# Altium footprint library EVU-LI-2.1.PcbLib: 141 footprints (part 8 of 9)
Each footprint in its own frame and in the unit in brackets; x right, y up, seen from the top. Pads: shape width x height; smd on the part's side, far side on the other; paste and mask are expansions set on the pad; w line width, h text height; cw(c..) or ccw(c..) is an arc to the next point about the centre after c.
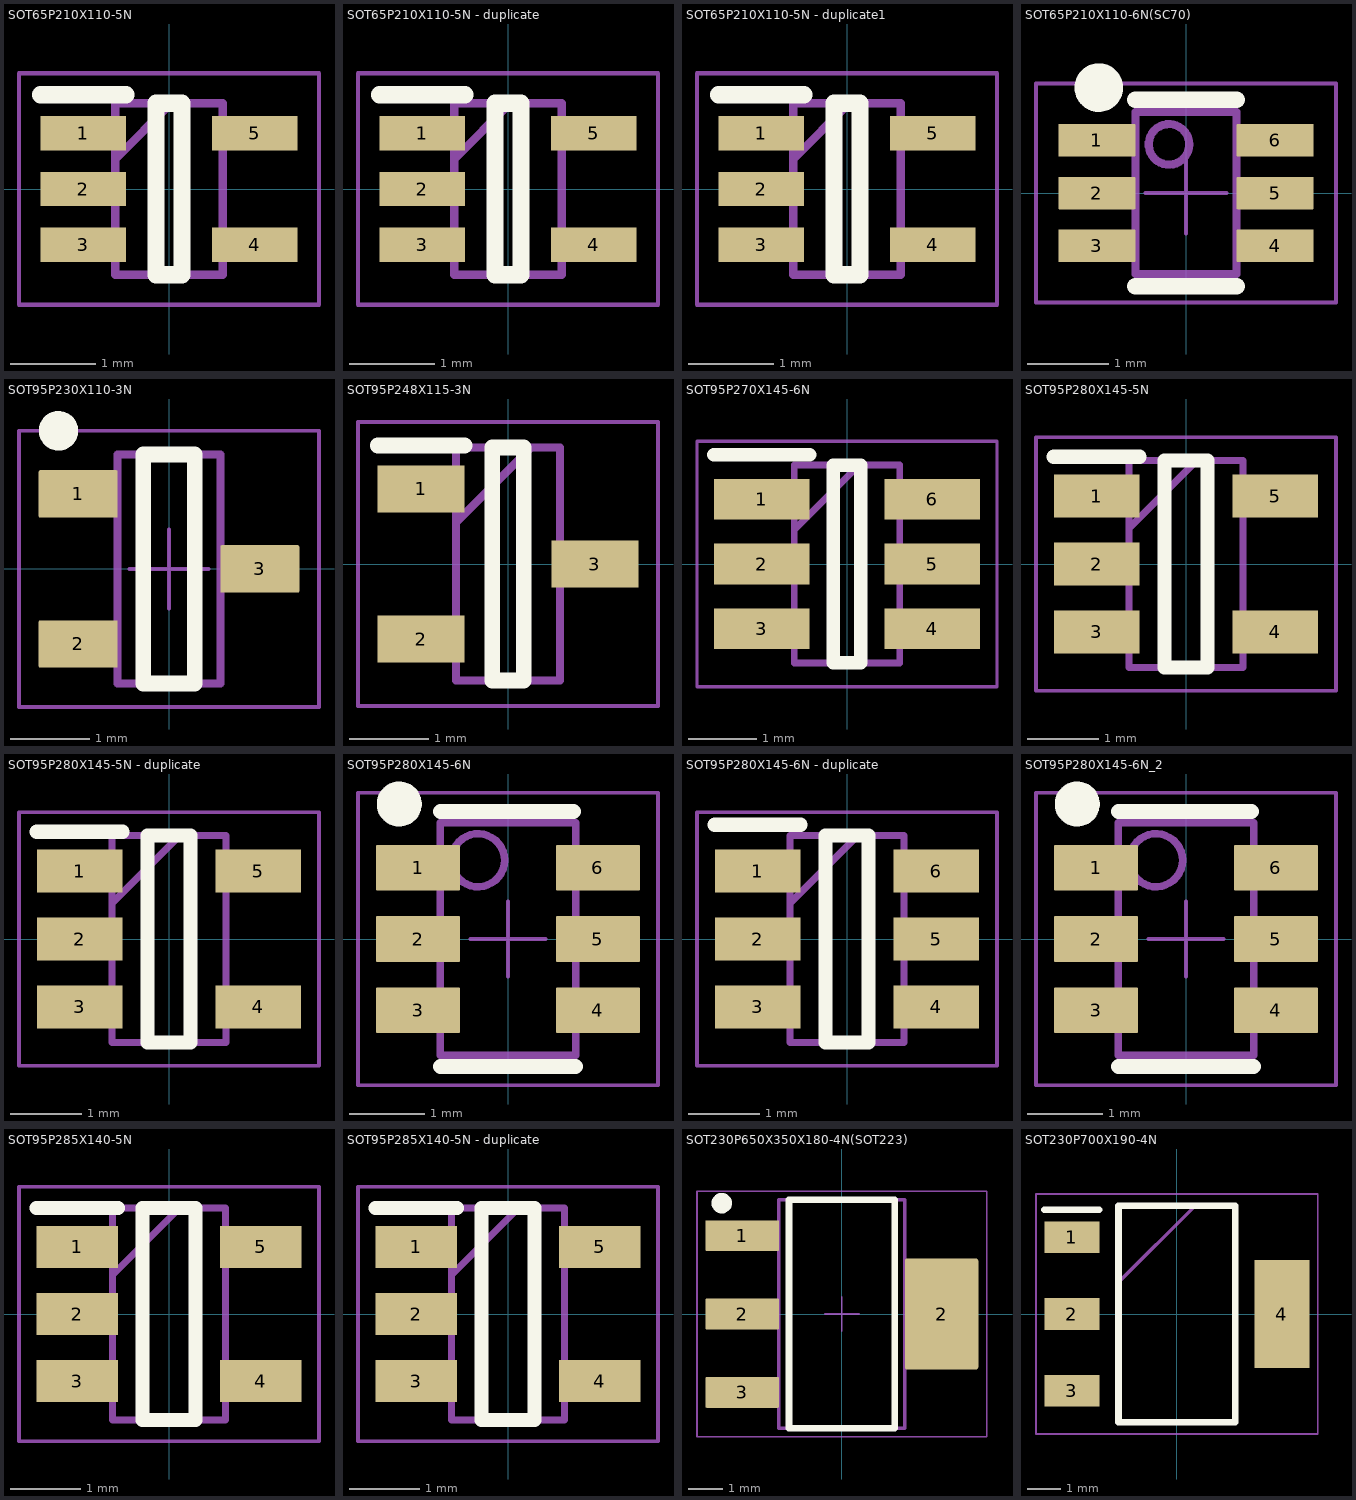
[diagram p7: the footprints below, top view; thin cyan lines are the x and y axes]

## SOT65P210X110-5N [mm]
pads (5):
  rect 1x0.4 smd: 1(-1,0.65) 2(-1,0) 3(-1,-0.65) 4(1,-0.65) 5(1,0.65)
Top Overlay:
  lines w0.2: -1.5,1.1 -0.5,1.1 ; -0.15,-1 -0.15,1 0.15,1 0.15,-1 -0.15,-1
Mechanical 13:
  lines w0.1: -0.625,0.35 0.025,1 ; -0.625,-1 -0.625,1 0.625,1 0.625,-1 -0.625,-1
Top Courtyard:
  lines w0.05: -1.75,-1.35 -1.75,1.35 1.75,1.35 1.75,-1.35 -1.75,-1.35
3D body "ZXRE160H5TA.stp": height 1.1, standoff 0, extent -1.05,-1 1.05,1

## SOT65P210X110-5N - duplicate [mm]
pads (5):
  rect 1x0.4 smd: 1(-1,0.65) 2(-1,0) 3(-1,-0.65) 4(1,-0.65) 5(1,0.65)
Top Overlay:
  lines w0.2: -1.5,1.1 -0.5,1.1 ; -0.15,-1 0.15,-1 0.15,1 -0.15,1 -0.15,-1
Mechanical 13:
  lines w0.1: -0.625,0.35 0.025,1 ; -0.625,-1 0.625,-1 0.625,1 -0.625,1 -0.625,-1
Top Courtyard:
  lines w0.05: -1.75,-1.35 1.75,-1.35 1.75,1.35 -1.75,1.35 -1.75,-1.35
3D body "ZXRE160H5TA.stp": height 1.1, standoff 0, extent -1.05,-1 1.05,1

## SOT65P210X110-5N - duplicate1 [mm]
pads (5):
  rect 1x0.4 smd: 1(-1,0.65) 2(-1,0) 3(-1,-0.65) 4(1,-0.65) 5(1,0.65)
Top Overlay:
  lines w0.2: -1.5,1.1 -0.5,1.1 ; -0.15,-1 -0.15,1 0.15,1 0.15,-1 -0.15,-1
Assembly Notes:
  lines w0.1: -0.625,0.35 0.025,1 ; -0.625,-1 -0.625,1 0.625,1 0.625,-1 -0.625,-1
Top Courtyard:
  lines w0.05: -1.75,-1.35 -1.75,1.35 1.75,1.35 1.75,-1.35 -1.75,-1.35
3D body "ZXRE160H5TA.stp": height 1.1, standoff 0, extent -1.05,-1 1.05,1

## SOT65P210X110-6N(SC70) [mm]
height 1.1
pads (6):
  rrect5% 0.95x0.4 smd mask+0.07: 1(-1.1,0.65) 2(-1.1,0) 3(-1.1,-0.65) 4(1.1,-0.65) 5(1.1,0) 6(1.1,0.65)
Top Overlay:
  circle w0.3: c-1.075,1.3 r0.15
  lines w0.2: -0.625,-1.15 0.625,-1.15 ; -0.625,1.15 0.625,1.15
Top Assembly:
  circle w0.1: c-0.21,0.6 r0.25
  lines w0.1: -0.625,-1 -0.625,1 0.625,1 0.625,-1 -0.625,-1
Top Designator:
  text ".Designator" at 0.3,-3.25 h1.5
Mechanical 9:
  text ".MARK" at 0.254,-1.778 h1.2
Top Courtyard:
  lines w0.05: -0.5,0 0.5,0 ; 0,-0.5 0,0.5 ; -1.85,-1.35 -1.85,1.35 1.85,1.35 1.85,-1.35 -1.85,-1.35
3D body: height 1.11, standoff 1.1, extent -0.473,0.376 0.025,0.875
3D body "SOT23-6-65P(DCK).STEP": height 1.1, standoff 0, extent -1.2,-1.05 1.2,1.05

## SOT95P230X110-3N [mm] "SOT95P230X110-3N"
height 1.1
pads (3):
  rrect5% 1x0.6 smd mask+0.05: 1(-1.15,0.95) 2(-1.15,-0.95) 3(1.15,0)
Top Overlay:
  circle w0.25: c-1.4,1.75 r0.125
  lines w0.2: -0.325,-1.45 0.325,-1.45 0.325,1.45 -0.325,1.45 -0.325,-1.45
Top Assembly:
  lines w0.1: -0.65,-1.45 0.65,-1.45 0.65,1.45 -0.65,1.45 -0.65,-1.45
Top Designator:
  text ".Designator" at -3.381,-0.211 h1.5
Mechanical 9:
  text ".MARK" at 0.329,-1.778 h1.2
Top Courtyard:
  lines w0.05: -0.5,0 0.5,0 ; 0,-0.5 0,0.5 ; -1.9,-1.75 1.9,-1.75 1.9,1.75 -1.9,1.75 -1.9,-1.75
3D body "SOT-23.STEP": height 1.1, standoff 0, extent -1.35,-1.55 1.35,1.55

## SOT95P248X115-3N [mm]
pads (3):
  rect 1.1x0.6 smd: 1(-1.1,0.95) 2(-1.1,-0.95) 3(1.1,0)
Top Overlay:
  lines w0.2: -1.65,1.5 -0.55,1.5 ; -0.2,-1.475 -0.2,1.475 0.2,1.475 0.2,-1.475 -0.2,-1.475
Mechanical 13:
  lines w0.1: -0.658,0.525 0.292,1.475 ; -0.658,-1.475 -0.658,1.475 0.658,1.475 0.658,-1.475 -0.658,-1.475
Top Courtyard:
  lines w0.05: -1.9,-1.8 -1.9,1.8 1.9,1.8 1.9,-1.8 -1.9,-1.8
3D body "BZX84C4V7-E3-08.stp": height 1.15, standoff 0, extent -1.238,-1.475 1.238,1.475

## SOT95P270X145-6N [mm]
pads (6):
  rect 1.4x0.6 smd: 1(-1.25,0.95) 2(-1.25,0) 3(-1.25,-0.95) 4(1.25,-0.95) 5(1.25,0) 6(1.25,0.95)
Top Overlay:
  lines w0.2: -1.95,1.6 -0.55,1.6 ; -0.2,-1.45 -0.2,1.45 0.2,1.45 0.2,-1.45 -0.2,-1.45
Mechanical 13:
  lines w0.1: -0.775,0.5 0.175,1.45 ; -0.775,-1.45 -0.775,1.45 0.775,1.45 0.775,-1.45 -0.775,-1.45
Top Courtyard:
  lines w0.05: -2.2,-1.8 -2.2,1.8 2.2,1.8 2.2,-1.8 -2.2,-1.8
3D body "93LC56BT-E_OT.stp": height 1.45, standoff 0, extent -1.35,-1.45 1.35,1.45

## SOT95P280X145-5N [mm]
pads (5):
  rect 1.2x0.6 smd: 1(-1.25,0.95) 2(-1.25,0) 3(-1.25,-0.95) 4(1.25,-0.95) 5(1.25,0.95)
Top Overlay:
  lines w0.2: -1.85,1.5 -0.65,1.5 ; -0.3,-1.45 0.3,-1.45 0.3,1.45 -0.3,1.45 -0.3,-1.45
Mechanical 13:
  lines w0.1: -0.8,0.5 0.15,1.45 ; -0.8,-1.45 0.8,-1.45 0.8,1.45 -0.8,1.45 -0.8,-1.45
Top Courtyard:
  lines w0.05: -2.1,-1.775 2.1,-1.775 2.1,1.775 -2.1,1.775 -2.1,-1.775
3D body "LMV331IDBVR.stp": height 1.2, standoff 0, extent -1.4,-1.45 1.4,1.45

## SOT95P280X145-5N - duplicate [mm]
pads (5):
  rect 1.2x0.6 smd: 1(-1.25,0.95) 2(-1.25,0) 3(-1.25,-0.95) 4(1.25,-0.95) 5(1.25,0.95)
Top Overlay:
  lines w0.2: -1.85,1.5 -0.65,1.5 ; -0.3,-1.45 -0.3,1.45 0.3,1.45 0.3,-1.45 -0.3,-1.45
Mechanical 13:
  lines w0.1: -0.8,0.5 0.15,1.45 ; -0.8,-1.45 -0.8,1.45 0.8,1.45 0.8,-1.45 -0.8,-1.45
Top Courtyard:
  lines w0.05: -2.1,-1.775 -2.1,1.775 2.1,1.775 2.1,-1.775 -2.1,-1.775
3D body "LMV331IDBVR.stp": height 1.2, standoff 0, extent -1.4,-1.45 1.4,1.45

## SOT95P280X145-6N [mm]
pads (6):
  rrect5% 1.12x0.61 smd mask+0.05: 1(-1.2,0.95) 2(-1.2,0) 3(-1.2,-0.95) 4(1.2,-0.95) 5(1.2,0) 6(1.2,0.95)
Top Overlay:
  circle w0.3: c-1.45,1.8 r0.15
  lines w0.2: -0.9,-1.7 0.9,-1.7 ; -0.9,1.7 0.875,1.7
Top Assembly:
  circle w0.1: c-0.4,1.05 r0.354
  lines w0.1: -0.9,-1.55 -0.9,1.55 0.9,1.55 0.9,-1.55 -0.9,-1.55
Top Designator:
  text ".Designator" at -3.25,-0.3 h1.5
Mechanical 9:
  text ".MARK" at 0.45,-1.675 h1.2
Top Courtyard:
  lines w0.05: -0.5,0 0.5,0 ; 0,-0.5 0,0.5 ; -2,-1.95 -2,1.95 2,1.95 2,-1.95 -2,-1.95
3D body "SOT-23-6_DBV.STEP": height 1.45, standoff 0, extent -1.417,-1.55 1.418,1.55
3D body: height 1.46, standoff 1.45, extent -0.498,0.801 0,1.3

## SOT95P280X145-6N - duplicate [mm]
pads (6):
  rect 1.2x0.6 smd: 1(-1.25,0.95) 2(-1.25,0) 3(-1.25,-0.95) 4(1.25,-0.95) 5(1.25,0) 6(1.25,0.95)
Top Overlay:
  lines w0.2: -1.85,1.6 -0.65,1.6 ; -0.3,-1.45 -0.3,1.45 0.3,1.45 0.3,-1.45 -0.3,-1.45
Mechanical 13:
  lines w0.1: -0.8,0.5 0.15,1.45 ; -0.8,-1.45 -0.8,1.45 0.8,1.45 0.8,-1.45 -0.8,-1.45
Top Courtyard:
  lines w0.05: -2.1,-1.775 -2.1,1.775 2.1,1.775 2.1,-1.775 -2.1,-1.775
3D body "LMR51610XDBVR.stp": height 1.45, standoff 0, extent -1.4,-1.45 1.4,1.45

## SOT95P280X145-6N_2 [mm]
pads (6):
  rrect5% 1.12x0.61 smd mask+0.05: 1(-1.2,0.95) 2(-1.2,0) 3(-1.2,-0.95) 4(1.2,-0.95) 5(1.2,0) 6(1.2,0.95)
Top Overlay:
  circle w0.3: c-1.45,1.8 r0.15
  lines w0.2: -0.9,-1.7 0.9,-1.7 ; -0.9,1.7 0.875,1.7
Top Assembly:
  circle w0.1: c-0.4,1.05 r0.354
  lines w0.1: -0.9,-1.55 -0.9,1.55 0.9,1.55 0.9,-1.55 -0.9,-1.55
Top Designator:
  text ".Designator" at -3.25,-0.3 h1.5
Mechanical 9:
  text ".MARK" at 0.45,-1.675 h1.2
Top Courtyard:
  lines w0.05: -0.5,0 0.5,0 ; 0,-0.5 0,0.5 ; -2,-1.95 -2,1.95 2,1.95 2,-1.95 -2,-1.95
3D body "SOT-23-6_DBV.STEP": height 1.45, standoff 0, extent -1.417,-1.55 1.418,1.55
3D body: height 1.46, standoff 1.45, extent -0.498,0.801 0,1.3

## SOT95P285X140-5N [mm]
pads (5):
  rect 1.15x0.6 smd: 1(-1.3,0.95) 2(-1.3,0) 3(-1.3,-0.95) 4(1.3,-0.95) 5(1.3,0.95)
Top Overlay:
  lines w0.2: -1.875,1.5 -0.725,1.5 ; -0.375,-1.5 -0.375,1.5 0.375,1.5 0.375,-1.5 -0.375,-1.5
Mechanical 13:
  lines w0.1: -0.8,0.55 0.15,1.5 ; -0.8,-1.5 -0.8,1.5 0.8,1.5 0.8,-1.5 -0.8,-1.5
Top Courtyard:
  lines w0.05: -2.125,-1.8 -2.125,1.8 2.125,1.8 2.125,-1.8 -2.125,-1.8
3D body "AP2191WG-7.stp": height 1.4, standoff 0, extent -1.425,-1.5 1.425,1.5

## SOT95P285X140-5N - duplicate [mm]
pads (5):
  rect 1.15x0.6 smd: 1(-1.3,0.95) 2(-1.3,0) 3(-1.3,-0.95) 4(1.3,-0.95) 5(1.3,0.95)
Top Overlay:
  lines w0.2: -1.875,1.5 -0.725,1.5 ; -0.375,-1.5 -0.375,1.5 0.375,1.5 0.375,-1.5 -0.375,-1.5
Mechanical 13:
  lines w0.1: -0.8,0.55 0.15,1.5 ; -0.8,-1.5 -0.8,1.5 0.8,1.5 0.8,-1.5 -0.8,-1.5
Top Courtyard:
  lines w0.05: -2.125,-1.8 -2.125,1.8 2.125,1.8 2.125,-1.8 -2.125,-1.8
3D body "AP2191WG-7.stp": height 1.4, standoff 0, extent -1.425,-1.5 1.425,1.5

## SOT230P650X350X180-4N(SOT223) [mm]
pads (4):
  rrect5% 2.15x0.9 smd: 1(-2.925,2.3) 2(-2.925,0) 3(-2.925,-2.3)
  rrect5% 2.15x3.25 smd: 2(2.925,0)
Top Overlay:
  circle w0.3: c-3.525,3.25 r0.15
  lines w0.2: -1.55,-3.35 1.55,-3.35 1.55,3.35 -1.55,3.35 -1.55,-3.35
Top Assembly:
  lines w0.1: -1.85,-3.35 1.85,-3.35 1.85,3.35 -1.85,3.35 -1.85,-3.35
Top Designator:
  text ".Designator" at -3.375,-0.35 h1.5
Mechanical 9:
  text ".MARK" at -1.65,-0.365 h1.2
Top Courtyard:
  lines w0.05: -0.5,0 0.5,0 ; 0,-0.5 0,0.5 ; -4.25,-3.6 4.25,-3.6 4.25,3.6 -4.25,3.6 -4.25,-3.6
3D body "SOT230P700X180-4N.step": height 1.8, standoff 0, extent -3.5,-3.35 3.5,3.35

## SOT230P700X190-4N [mm]
pads (4):
  rect 1.65x0.95 smd: 1(-3.15,2.3) 2(-3.15,0) 3(-3.15,-2.3)
  rect 1.65x3.25 smd: 4(3.15,0)
Top Overlay:
  lines w0.2: -3.975,3.125 -2.325,3.125 ; -1.75,-3.25 -1.75,3.25 1.75,3.25 1.75,-3.25 -1.75,-3.25
Mechanical 13:
  lines w0.1: -1.75,0.95 0.55,3.25 ; -1.75,-3.25 -1.75,3.25 1.75,3.25 1.75,-3.25 -1.75,-3.25
Top Courtyard:
  lines w0.05: -4.225,-3.6 -4.225,3.6 4.225,3.6 4.225,-3.6 -4.225,-3.6
3D body "LD1117S50TR.stp": height 1.83, standoff -0.02, extent -3.5,-3.249 3.5,3.249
